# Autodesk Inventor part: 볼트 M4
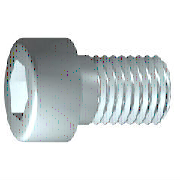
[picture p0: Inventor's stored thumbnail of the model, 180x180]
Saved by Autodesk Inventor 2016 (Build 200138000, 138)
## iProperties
IsCustomPart: 0
Created: 2012-02
Part Number: 볼트 M4
Material: 스테인리스강
Description: 6각 소켓 머리 캡 나사
Document SubType Name: Modeling
Standard: ISO 4762
Designer: mduedu
Standard Revision: Fourth edition 2004-03-01
Standards Organization: ISO
Language: ko-KR
Size Designation: M4 x 10
Categories: <MemberInstance><Categories><Category DisplayName="조임쇠" InternalName="e4da775c-781d-43d5-af7c-5136215cf5a6" Mnemonic="FSTN"><Category DisplayName="볼트" InternalN
Density: 8.08 g/cm^3
Appearance: 반광택
Author: mduedu
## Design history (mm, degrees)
sketch "스케치1"
  geometry: L1 (-1, 0)-(10, 0); L2 (10, 0)-(10, 2); L3 (10, 2)-(1.75, 2); L4 (1.75, 2)-(1.32, 2); L5 (1.32, 2)-(0, 2); L6 (0, 2)-(0, 3.5); L7 (0, 3.5)-(-4, 3.5); L8 (-4, 3.5)-(-4, 1.732); L9 (-4, 1.732)-(-2, 1.732); L10 (-2, 1.732)-(-1, 0); L11 (-6.8, 0)-(12.8, 0) reference; L12 (0, -0.7)-(0, 4.2) reference; L13 (1.75, 2)-(0, 2)
  constraints: 22 end point, 6 parallel, 2 collinear, 2 perpendicular, 1 horizontal, 1 point on line
  dimensions: "d1" = 8.25 distance from line of L3.end L2 (= GEL); "d2" = 0.42952 distance of L4.end L3.end (computed from GAL); "d3" = 4 distance between parallel lines of L8 L6 (= KOH); "d4" = 2 distance of L8.end L9.end (= INTI); "d5" = 60 deg angle of L10 L1; "d6" = 4 diameter of L3 L1 (= GD); "d7" = 4 diameter of L5 L1 (= BDM); "d8" = 3.4641 diameter of L9 L1 (= 1.1547 x SW); "d9" = 7 diameter of L7 L1 (= KOD); "d26" = 10 distance between parallel lines of L12 L2 (= NLG)
revolve "본체" sketch "스케치1" stored, may be unused: angle "d10" = 90 deg
sketch "스케치2"
  geometry: L1 (0, -4.9)-(0, 4.9) reference; L2 (-4.9, 0)-(4.9, 0) reference; L3 (1.732, 0)-(0.866, -1.5); L4 (0.866, -1.5)-(-0.866, -1.5); L5 (-0.866, -1.5)-(-1.732, 0); L6 (-1.732, 0)-(-0.866, 1.5); L7 (-0.866, 1.5)-(0.866, 1.5); L8 (0.866, 1.5)-(1.732, 0); 2 further points
  constraints: 12 end point, 1 coincident, 1 horizontal alignment, 1 point on line, 12 other
extrude "슬롯" join sketch "스케치2" stored distance "d11" = 10; taper "d12" = 0 deg
workplane "Work Plane1"
fillet "Fillet2" dims "d30" = 0.1 (= R)
body "Solid1"
fillet "모깎기1" dims "d17" = 0.4 (= RR)
feature "스레드" dims "d13" = 8.25 (= GEL), "d14" = 0
chamfer "모따기1" distance "d15" = 0.42941 (= -0.5 x SPD + 0.5 x GD); stored, may be unused: second distance "d16" = 0.42941 (= GUL), angle "d27" = 45 deg
other parameters: "GD" = 4 [user parameter; used in 2 equation terms], "NLG" = 10 [user parameter; used in 1 equation term], "GEL" = 8.25 [user parameter; used in 2 equation terms], "KOD" = 7 [user parameter; used in 1 equation term], "KOH" = 4 [user parameter; used in 1 equation term], "INTI" = 2 [user parameter; used in 1 equation term], "GAL" = 0.42941 (= 0.61345 x PTC) [user parameter; used in 1 equation term], "GUL" = 0.42941 (= 0.61345 x PTC) [user parameter; used in 1 equation term], "BDM" = 4 (= NND) [user parameter; used in 1 equation term], "SW" = 3 [user parameter; used in 2 equation terms], "RR" = 0.4 [user parameter; used in 1 equation term], "SPD" = 3.14117 (= NND - 1.2269 x PTC) [user parameter; used in 1 equation term], "d19" = 0, "d28" = 0, "d29" = 0, "R" = 0.1 [user parameter; used in 1 equation term], "TOA" = 30 deg [user parameter], "GD1" = 3.14117 (= THREADDIA - 1.2269 x PTC) [user parameter], "THREADDIA" = 4 [user parameter; used in 1 equation term], "FAWI" = 45 deg [user parameter], "TPU" = 14.28571 (computed from PTC) [user parameter], "PTC" = 0.7 [user parameter; used in 5 equation terms], "NND" = 4 [user parameter; used in 2 equation terms], "E0" = 3.465 (= 1.155 x SW) [user parameter]
